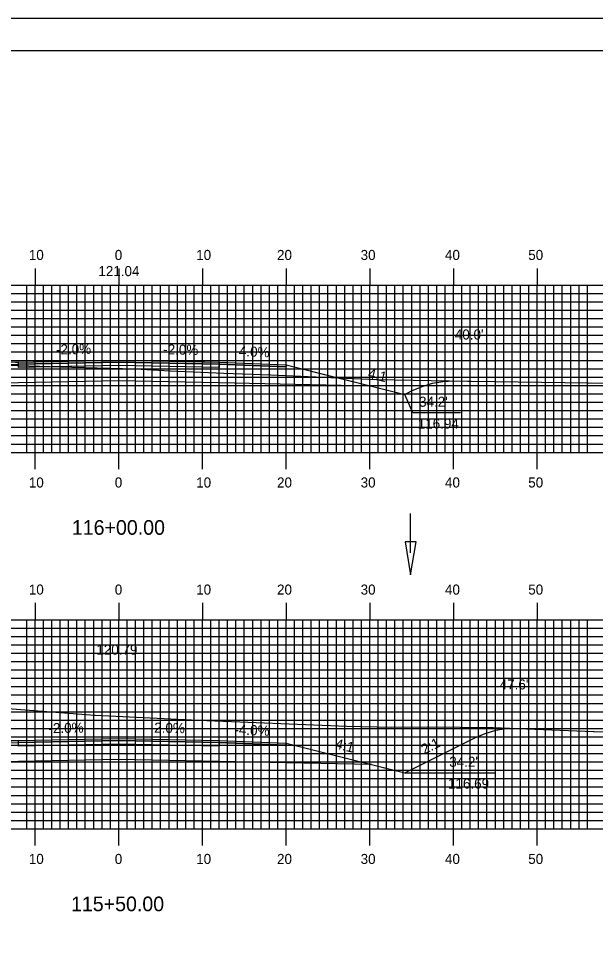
# Model space of a CAD drawing. Extents: x 1770842 to 1771185, y 442591 to 442811.
# Drawn here: x 1770995.6 to 1771064.5, y 442700.5 to 442810.5 of the extents above; entities that cross this region are included whole.
import ezdxf

# ---------------------------------------------------------------- set-up
doc = ezdxf.new("R2010")
doc.units = 0
for name, color, linetype in [('ANNOTATION', 7, 'Continuous'), ('BORDER', 7, 'Continuous'), ('D_Drainage_Ditch_Line', 7, 'Continuous'), ('D_Roadway_Centerline', 7, 'Continuous'), ('D_Roadway_Centerline_Text', 7, 'Continuous'), ('D_Roadway_Edge_Shoulder', 7, 'Continuous'), ('D_Roadway_Edge_TW', 7, 'Continuous'), ('D_Roadway_Pavement', 7, 'Continuous'), ('D_Roadway_SlopeLines', 7, 'Continuous'), ('D_Roadway_SubGrade', 7, 'Continuous'), ('D_Text_Standard', 7, 'Continuous'), ('H_V ANNOTATION', 7, 'Continuous'), ('MAJOR', 7, 'Continuous'), ('MINOR', 7, 'Continuous'), ('PDRAIN', 7, 'Continuous'), ('PLOT BOUNDARY', 7, 'Continuous'), ('S_Roadway_Centerline', 7, 'Continuous')]:
    doc.layers.add(name, color=color, linetype=linetype)

msp = doc.modelspace()

# ---------------------------------------------------------------- linework, layer by layer
at = {"layer": 'ANNOTATION'}
msp.add_lwpolyline([(1771048.38, 442763.4), (1771042.69, 442763.4), (1771041.73, 442765.6)], dxfattribs=at)
at = {"layer": 'BORDER'}
msp.add_lwpolyline([(1770857.95, 442596.67), (1771177.95, 442596.67), (1771177.95, 442806.67), (1770857.95, 442806.67)], close=True, dxfattribs=at)
at = {"layer": 'D_Drainage_Ditch_Line'}
msp.add_line((1771042.42, 442746.66), (1771042.42, 442751.36), dxfattribs=at)
msp.add_lwpolyline([(1771043.07, 442747.97), (1771041.76, 442747.97), (1771042.42, 442744.03)], close=True, dxfattribs=at)
at = {"layer": 'D_Roadway_Centerline'}
for points in [[(1770995.21, 442769.45), (1770995.55, 442769.47), (1770997.35, 442769.5), (1771007.55, 442769.71), (1771010.77, 442769.64), (1771019.55, 442769.47), (1771027.55, 442769.15), (1771033.74, 442767.6), (1771037.73, 442766.6), (1771041.73, 442765.6), (1771042.54, 442766.01), (1771043.79, 442766.55), (1771045.04, 442766.93), (1771046.29, 442767.15), (1771047.43, 442767.21), (1771047.54, 442767.21)], [(1770993.94, 442724.15), (1770995.55, 442724.22), (1770995.56, 442724.22), (1771007.55, 442724.46), (1771007.56, 442724.46), (1771019.55, 442724.22), (1771019.56, 442724.22), (1771022.63, 442724.09), (1771027.55, 442723.9), (1771037.73, 442721.35), (1771040.09, 442720.76), (1771041.73, 442720.35), (1771050.1, 442724.54), (1771051.35, 442725.08), (1771052.6, 442725.45), (1771053.85, 442725.65), (1771055.1, 442725.68)]]:
    msp.add_lwpolyline(points, dxfattribs=at)
at = {"layer": 'D_Roadway_Edge_Shoulder'}
for points in [[(1770995.55, 442769.47), (1770987.55, 442769.15), (1770987.55, 442768.9), (1770995.55, 442769.22)], [(1771019.55, 442769.47), (1771027.55, 442769.15), (1771027.55, 442768.9), (1771019.55, 442769.22)], [(1770995.55, 442724.22), (1770987.55, 442723.9), (1770987.55, 442723.65), (1770995.55, 442723.97)], [(1771019.55, 442724.22), (1771027.55, 442723.9), (1771027.55, 442723.65), (1771019.55, 442723.97)]]:
    msp.add_lwpolyline(points, close=True, dxfattribs=at)
at = {"layer": 'D_Roadway_Edge_TW'}
for points in [[(1770995.55, 442769.22), (1770995.55, 442769.47), (1771007.55, 442769.71), (1771019.55, 442769.47), (1771019.55, 442769.22), (1771007.55, 442769.46)], [(1770995.55, 442723.97), (1770995.55, 442724.22), (1771007.55, 442724.46), (1771019.55, 442724.22), (1771019.55, 442723.97), (1771007.55, 442724.21)]]:
    msp.add_lwpolyline(points, close=True, dxfattribs=at)
at = {"layer": 'D_Roadway_Pavement'}
for points in [[(1770995.55, 442768.8), (1770995.55, 442769.22), (1771007.55, 442769.46), (1771019.55, 442769.22), (1771019.55, 442768.8), (1771007.55, 442769.04)], [(1770995.55, 442723.55), (1770995.55, 442723.97), (1771007.55, 442724.21), (1771019.55, 442723.97), (1771019.55, 442723.55), (1771007.55, 442723.79)]]:
    msp.add_lwpolyline(points, close=True, dxfattribs=at)
at = {"layer": 'D_Roadway_SlopeLines'}
for points in [[(1771027.55, 442769.15), (1771041.73, 442765.6)], [(1771041.73, 442765.6), (1771042.54, 442766.01), (1771043.79, 442766.55), (1771045.04, 442766.93), (1771046.29, 442767.15), (1771047.54, 442767.21)], [(1771041.73, 442720.35), (1771050.1, 442724.54), (1771051.35, 442725.08), (1771052.6, 442725.45), (1771053.85, 442725.65), (1771055.1, 442725.68)], [(1771027.55, 442723.9), (1771041.73, 442720.35)]]:
    msp.add_lwpolyline(points, dxfattribs=at)
at = {"layer": 'D_Roadway_SubGrade'}
for points in [[(1770995.55, 442766.97), (1770977.38, 442766.6), (1770987.55, 442769.15), (1770987.55, 442768.9), (1770995.55, 442769.22), (1771007.55, 442769.46), (1771019.55, 442769.22), (1771027.55, 442768.9), (1771027.55, 442769.15), (1771037.73, 442766.6), (1771019.55, 442766.97), (1771007.55, 442767.21)], [(1770995.55, 442721.72), (1770977.38, 442721.35), (1770987.55, 442723.9), (1770987.55, 442723.65), (1770995.55, 442723.97), (1771007.55, 442724.21), (1771019.55, 442723.97), (1771027.55, 442723.65), (1771027.55, 442723.9), (1771037.73, 442721.35), (1771019.55, 442721.72), (1771007.55, 442721.96)]]:
    msp.add_lwpolyline(points, close=True, dxfattribs=at)
at = {"layer": 'MAJOR'}
for p, q in [((1770997.55, 442780.67), (1770997.55, 442778.67)), ((1771007.55, 442780.67), (1771007.55, 442778.67)), ((1771017.55, 442780.67), (1771017.55, 442778.67)), ((1771027.55, 442780.67), (1771027.55, 442778.67)), ((1771037.55, 442780.67), (1771037.55, 442778.67)), ((1771047.55, 442780.67), (1771047.55, 442778.67)), ((1771057.55, 442780.67), (1771057.55, 442778.67)), ((1770867.55, 442778.67), (1771147.55, 442778.67)), ((1770867.55, 442778.67), (1771147.55, 442778.67)), ((1770997.55, 442758.67), (1770997.55, 442778.67)), ((1771007.55, 442758.67), (1771007.55, 442778.67)), ((1771017.55, 442758.67), (1771017.55, 442778.67)), ((1771027.55, 442758.67), (1771027.55, 442778.67)), ((1771037.55, 442758.67), (1771037.55, 442778.67)), ((1771047.55, 442758.67), (1771047.55, 442778.67)), ((1771057.55, 442758.67), (1771057.55, 442778.67)), ((1770867.55, 442773.67), (1771147.55, 442773.67)), ((1770867.55, 442768.67), (1771147.55, 442768.67)), ((1770867.55, 442763.67), (1771147.55, 442763.67)), ((1770867.55, 442758.67), (1771147.55, 442758.67)), ((1770867.55, 442758.67), (1771147.55, 442758.67)), ((1770997.55, 442756.66), (1770997.55, 442758.67)), ((1771007.55, 442756.66), (1771007.55, 442758.67)), ((1771017.55, 442756.66), (1771017.55, 442758.67)), ((1771027.55, 442756.66), (1771027.55, 442758.67)), ((1771037.55, 442756.66), (1771037.55, 442758.67)), ((1771047.55, 442756.66), (1771047.55, 442758.67)), ((1771057.55, 442756.66), (1771057.55, 442758.67)), ((1770997.55, 442740.67), (1770997.55, 442738.67)), ((1771007.55, 442740.67), (1771007.55, 442738.67)), ((1771017.55, 442740.67), (1771017.55, 442738.67)), ((1771027.55, 442740.67), (1771027.55, 442738.67)), ((1771037.55, 442740.67), (1771037.55, 442738.67)), ((1771047.55, 442740.67), (1771047.55, 442738.67)), ((1771057.55, 442740.67), (1771057.55, 442738.67)), ((1770867.55, 442738.67), (1771147.55, 442738.67)), ((1770867.55, 442738.67), (1771147.55, 442738.67)), ((1770997.55, 442713.67), (1770997.55, 442738.67)), ((1771007.55, 442713.67), (1771007.55, 442738.67)), ((1771017.55, 442713.67), (1771017.55, 442738.67)), ((1771027.55, 442713.67), (1771027.55, 442738.67)), ((1771037.55, 442713.67), (1771037.55, 442738.67)), ((1771047.55, 442713.67), (1771047.55, 442738.67)), ((1771057.55, 442713.67), (1771057.55, 442738.67)), ((1770867.55, 442733.67), (1771147.55, 442733.67)), ((1770867.55, 442728.67), (1771147.55, 442728.67)), ((1770867.55, 442723.67), (1771147.55, 442723.67)), ((1770867.55, 442718.67), (1771147.55, 442718.67)), ((1770867.55, 442713.67), (1771147.55, 442713.67)), ((1770867.55, 442713.67), (1771147.55, 442713.67)), ((1770997.55, 442711.66), (1770997.55, 442713.67)), ((1771007.55, 442711.66), (1771007.55, 442713.67)), ((1771017.55, 442711.66), (1771017.55, 442713.67)), ((1771027.55, 442711.66), (1771027.55, 442713.67)), ((1771037.55, 442711.66), (1771037.55, 442713.67)), ((1771047.55, 442711.66), (1771047.55, 442713.67)), ((1771057.55, 442711.66), (1771057.55, 442713.67))]:
    msp.add_line(p, q, dxfattribs=at)
at = {"layer": 'MINOR'}
for p, q in [((1770996.55, 442758.67), (1770996.55, 442778.67)), ((1770998.55, 442758.67), (1770998.55, 442778.67)), ((1770999.55, 442758.67), (1770999.55, 442778.67)), ((1771000.55, 442758.67), (1771000.55, 442778.67)), ((1771001.55, 442758.67), (1771001.55, 442778.67)), ((1771002.55, 442758.67), (1771002.55, 442778.67)), ((1771003.55, 442758.67), (1771003.55, 442778.67)), ((1771004.55, 442758.67), (1771004.55, 442778.67)), ((1771005.55, 442758.67), (1771005.55, 442778.67)), ((1771006.55, 442758.67), (1771006.55, 442778.67)), ((1771008.55, 442758.67), (1771008.55, 442778.67)), ((1771009.55, 442758.67), (1771009.55, 442778.67)), ((1771010.55, 442758.67), (1771010.55, 442778.67)), ((1771011.55, 442758.67), (1771011.55, 442778.67)), ((1771012.55, 442758.67), (1771012.55, 442778.67)), ((1771013.55, 442758.67), (1771013.55, 442778.67)), ((1771014.55, 442758.67), (1771014.55, 442778.67)), ((1771015.55, 442758.67), (1771015.55, 442778.67)), ((1771016.55, 442758.67), (1771016.55, 442778.67)), ((1771018.55, 442758.67), (1771018.55, 442778.67)), ((1771019.55, 442758.67), (1771019.55, 442778.67)), ((1771020.55, 442758.67), (1771020.55, 442778.67)), ((1771021.55, 442758.67), (1771021.55, 442778.67)), ((1771022.55, 442758.67), (1771022.55, 442778.67)), ((1771023.55, 442758.67), (1771023.55, 442778.67)), ((1771024.55, 442758.67), (1771024.55, 442778.67)), ((1771025.55, 442758.67), (1771025.55, 442778.67)), ((1771026.55, 442758.67), (1771026.55, 442778.67)), ((1771028.55, 442758.67), (1771028.55, 442778.67)), ((1771029.55, 442758.67), (1771029.55, 442778.67)), ((1771030.55, 442758.67), (1771030.55, 442778.67)), ((1771031.55, 442758.67), (1771031.55, 442778.67)), ((1771032.55, 442758.67), (1771032.55, 442778.67)), ((1771033.55, 442758.67), (1771033.55, 442778.67)), ((1771034.55, 442758.67), (1771034.55, 442778.67)), ((1771035.55, 442758.67), (1771035.55, 442778.67)), ((1771036.55, 442758.67), (1771036.55, 442778.67)), ((1771038.55, 442758.67), (1771038.55, 442778.67)), ((1771039.55, 442758.67), (1771039.55, 442778.67)), ((1771040.55, 442758.67), (1771040.55, 442778.67)), ((1771041.55, 442758.67), (1771041.55, 442778.67)), ((1771042.55, 442758.67), (1771042.55, 442778.67)), ((1771043.55, 442758.67), (1771043.55, 442778.67)), ((1771044.55, 442758.67), (1771044.55, 442778.67)), ((1771045.55, 442758.67), (1771045.55, 442778.67)), ((1771046.55, 442758.67), (1771046.55, 442778.67)), ((1771048.55, 442758.67), (1771048.55, 442778.67)), ((1771049.55, 442758.67), (1771049.55, 442778.67)), ((1771050.55, 442758.67), (1771050.55, 442778.67)), ((1771051.55, 442758.67), (1771051.55, 442778.67)), ((1771052.55, 442758.67), (1771052.55, 442778.67)), ((1771053.55, 442758.67), (1771053.55, 442778.67)), ((1771054.55, 442758.67), (1771054.55, 442778.67)), ((1771055.55, 442758.67), (1771055.55, 442778.67)), ((1771056.55, 442758.67), (1771056.55, 442778.67)), ((1771058.55, 442758.67), (1771058.55, 442778.67)), ((1771059.55, 442758.67), (1771059.55, 442778.67)), ((1771060.55, 442758.67), (1771060.55, 442778.67)), ((1771061.55, 442758.67), (1771061.55, 442778.67)), ((1771062.55, 442758.67), (1771062.55, 442778.67)), ((1771063.55, 442758.67), (1771063.55, 442778.67)), ((1770867.55, 442777.67), (1771147.55, 442777.67)), ((1770867.55, 442776.67), (1771147.55, 442776.67)), ((1770867.55, 442775.67), (1771147.55, 442775.67)), ((1770867.55, 442774.67), (1771147.55, 442774.67)), ((1770867.55, 442772.67), (1771147.55, 442772.67)), ((1770867.55, 442771.67), (1771147.55, 442771.67)), ((1770867.55, 442770.67), (1771147.55, 442770.67)), ((1770867.55, 442769.67), (1771147.55, 442769.67)), ((1770867.55, 442767.67), (1771147.55, 442767.67)), ((1770867.55, 442766.67), (1771147.55, 442766.67)), ((1770867.55, 442765.67), (1771147.55, 442765.67)), ((1770867.55, 442764.67), (1771147.55, 442764.67)), ((1770867.55, 442762.67), (1771147.55, 442762.67)), ((1770867.55, 442761.67), (1771147.55, 442761.67)), ((1770867.55, 442760.67), (1771147.55, 442760.67)), ((1770867.55, 442759.67), (1771147.55, 442759.67)), ((1770996.55, 442713.67), (1770996.55, 442738.67)), ((1770998.55, 442713.67), (1770998.55, 442738.67)), ((1770999.55, 442713.67), (1770999.55, 442738.67)), ((1771000.55, 442713.67), (1771000.55, 442738.67)), ((1771001.55, 442713.67), (1771001.55, 442738.67)), ((1771002.55, 442713.67), (1771002.55, 442738.67)), ((1771003.55, 442713.67), (1771003.55, 442738.67)), ((1771004.55, 442713.67), (1771004.55, 442738.67)), ((1771005.55, 442713.67), (1771005.55, 442738.67)), ((1771006.55, 442713.67), (1771006.55, 442738.67)), ((1771008.55, 442713.67), (1771008.55, 442738.67)), ((1771009.55, 442713.67), (1771009.55, 442738.67)), ((1771010.55, 442713.67), (1771010.55, 442738.67)), ((1771011.55, 442713.67), (1771011.55, 442738.67)), ((1771012.55, 442713.67), (1771012.55, 442738.67)), ((1771013.55, 442713.67), (1771013.55, 442738.67)), ((1771014.55, 442713.67), (1771014.55, 442738.67)), ((1771015.55, 442713.67), (1771015.55, 442738.67)), ((1771016.55, 442713.67), (1771016.55, 442738.67)), ((1771018.55, 442713.67), (1771018.55, 442738.67)), ((1771019.55, 442713.67), (1771019.55, 442738.67)), ((1771020.55, 442713.67), (1771020.55, 442738.67)), ((1771021.55, 442713.67), (1771021.55, 442738.67)), ((1771022.55, 442713.67), (1771022.55, 442738.67)), ((1771023.55, 442713.67), (1771023.55, 442738.67)), ((1771024.55, 442713.67), (1771024.55, 442738.67)), ((1771025.55, 442713.67), (1771025.55, 442738.67)), ((1771026.55, 442713.67), (1771026.55, 442738.67)), ((1771028.55, 442713.67), (1771028.55, 442738.67)), ((1771029.55, 442713.67), (1771029.55, 442738.67)), ((1771030.55, 442713.67), (1771030.55, 442738.67)), ((1771031.55, 442713.67), (1771031.55, 442738.67)), ((1771032.55, 442713.67), (1771032.55, 442738.67)), ((1771033.55, 442713.67), (1771033.55, 442738.67)), ((1771034.55, 442713.67), (1771034.55, 442738.67)), ((1771035.55, 442713.67), (1771035.55, 442738.67)), ((1771036.55, 442713.67), (1771036.55, 442738.67)), ((1771038.55, 442713.67), (1771038.55, 442738.67)), ((1771039.55, 442713.67), (1771039.55, 442738.67)), ((1771040.55, 442713.67), (1771040.55, 442738.67)), ((1771041.55, 442713.67), (1771041.55, 442738.67)), ((1771042.55, 442713.67), (1771042.55, 442738.67)), ((1771043.55, 442713.67), (1771043.55, 442738.67)), ((1771044.55, 442713.67), (1771044.55, 442738.67)), ((1771045.55, 442713.67), (1771045.55, 442738.67)), ((1771046.55, 442713.67), (1771046.55, 442738.67)), ((1771048.55, 442713.67), (1771048.55, 442738.67)), ((1771049.55, 442713.67), (1771049.55, 442738.67)), ((1771050.55, 442713.67), (1771050.55, 442738.67)), ((1771051.55, 442713.67), (1771051.55, 442738.67)), ((1771052.55, 442713.67), (1771052.55, 442738.67)), ((1771053.55, 442713.67), (1771053.55, 442738.67)), ((1771054.55, 442713.67), (1771054.55, 442738.67)), ((1771055.55, 442713.67), (1771055.55, 442738.67)), ((1771056.55, 442713.67), (1771056.55, 442738.67)), ((1771058.55, 442713.67), (1771058.55, 442738.67)), ((1771059.55, 442713.67), (1771059.55, 442738.67)), ((1771060.55, 442713.67), (1771060.55, 442738.67)), ((1771061.55, 442713.67), (1771061.55, 442738.67)), ((1771062.55, 442713.67), (1771062.55, 442738.67)), ((1771063.55, 442713.67), (1771063.55, 442738.67)), ((1770867.55, 442737.67), (1771147.55, 442737.67)), ((1770867.55, 442736.67), (1771147.55, 442736.67)), ((1770867.55, 442735.67), (1771147.55, 442735.67)), ((1770867.55, 442734.67), (1771147.55, 442734.67)), ((1770867.55, 442732.67), (1771147.55, 442732.67)), ((1770867.55, 442731.67), (1771147.55, 442731.67)), ((1770867.55, 442730.67), (1771147.55, 442730.67)), ((1770867.55, 442729.67), (1771147.55, 442729.67)), ((1770867.55, 442727.67), (1771147.55, 442727.67)), ((1770867.55, 442726.67), (1771147.55, 442726.67)), ((1770867.55, 442725.67), (1771147.55, 442725.67)), ((1770867.55, 442724.67), (1771147.55, 442724.67)), ((1770867.55, 442722.67), (1771147.55, 442722.67)), ((1770867.55, 442721.67), (1771147.55, 442721.67)), ((1770867.55, 442720.67), (1771147.55, 442720.67)), ((1770867.55, 442719.67), (1771147.55, 442719.67)), ((1770867.55, 442717.67), (1771147.55, 442717.67)), ((1770867.55, 442716.67), (1771147.55, 442716.67)), ((1770867.55, 442715.67), (1771147.55, 442715.67)), ((1770867.55, 442714.67), (1771147.55, 442714.67))]:
    msp.add_line(p, q, dxfattribs=at)
at = {"layer": 'PDRAIN'}
msp.add_line((1771041.73, 442720.35), (1771052.5, 442720.35), dxfattribs=at)
at = {"layer": 'PLOT BOUNDARY'}
msp.add_lwpolyline([(1770841.77, 442590.55), (1771181.77, 442590.55), (1771181.77, 442810.55), (1770841.77, 442810.55)], close=True, dxfattribs=at)
at = {"layer": 'S_Roadway_Centerline'}
for points in [[(1770933.71, 442771.31), (1770950.3, 442771.19), (1770961.31, 442770.9), (1770969.16, 442770.62), (1770978.29, 442769.86), (1770990.16, 442769.22), (1770991.62, 442769.16), (1771001.93, 442768.85), (1771009.49, 442768.67), (1771013.67, 442768.4), (1771020.09, 442768.15), (1771025.72, 442767.92), (1771030.17, 442767.73), (1771038.35, 442767.38), (1771049.28, 442767.18), (1771049.65, 442767.18), (1771069.27, 442766.89)], [(1770933.69, 442729.93), (1770944.44, 442729.3), (1770945.31, 442729.29), (1770946.7, 442729.26), (1770958.32, 442729.09), (1770965.48, 442728.91), (1770975.35, 442728.38), (1770979.99, 442728.18), (1770983.6, 442728.14), (1770993.2, 442728.13), (1771004.67, 442727.27), (1771004.7, 442727.26), (1771004.71, 442727.26), (1771017.09, 442726.64), (1771034.82, 442725.93), (1771040.18, 442725.84), (1771044.39, 442725.86), (1771052.3, 442725.8), (1771064.28, 442725.3), (1771064.35, 442725.29), (1771083.72, 442724.92)]]:
    msp.add_lwpolyline(points, dxfattribs=at)

# ---------------------------------------------------------------- texts
at = {"layer": 'ANNOTATION'}
for s, rotation, p in [('-2.0%', 1.1458, (1771000.06, 442770.36)), ('-2.0%', 358.8543, (1771012.85, 442770.4)), ('-4.0%', 357.7093, (1771021.35, 442770.2)), ('4:1', 345.9626, (1771037.24, 442767.59)), ('-2.0%', 1.1457, (1770999.16, 442725.09)), ('-2.0%', 358.8543, (1771011.24, 442725.18)), ('-4.0%', 357.7092, (1771021.35, 442724.95)), ('4:1', 345.9615, (1771033.33, 442723.31)), ('2:1', 26.5661, (1771044.06, 442722.55))]:
    msp.add_text(s, height=1.2, rotation=rotation, dxfattribs=at).set_placement(p)
for s, p in [("34.2'", (1771043.43, 442764.12)), ('116.94', (1771043.28, 442761.52)), ("34.2'", (1771047.04, 442721.08)), ('116.69', (1771046.89, 442718.48))]:
    msp.add_text(s, height=1.2, dxfattribs=at).set_placement(p)
at = {"layer": 'D_Roadway_Centerline'}
for s, p in [('C', (1771007.55, 442769.71)), ('L', (1771007.55, 442769.7)), ('C', (1771007.55, 442724.46)), ('L', (1771007.55, 442724.45))]:
    msp.add_text(s, height=0.0146, dxfattribs=at).set_placement(p)
at = {"layer": 'D_Roadway_Centerline_Text'}
for s, p in [('121.04', (1771005.11, 442779.74)), ('120.79', (1771004.87, 442734.49))]:
    msp.add_text(s, height=1.2, dxfattribs=at).set_placement(p)
at = {"layer": 'D_Text_Standard'}
for s, p in [("40.0'", (1771047.71, 442772.16)), ("47.6'", (1771053.07, 442730.33))]:
    msp.add_text(s, height=1.2, dxfattribs=at).set_placement(p)
at = {"layer": 'H_V ANNOTATION'}
for s, height, p in [('10', 1.2, (1770996.8, 442781.67)), ('0', 1.2, (1771007.07, 442781.67)), ('10', 1.2, (1771016.8, 442781.67)), ('20', 1.2, (1771026.46, 442781.67)), ('30', 1.2, (1771036.45, 442781.67)), ('40', 1.2, (1771046.53, 442781.67)), ('50', 1.2, (1771056.48, 442781.67)), ('10', 1.2, (1770996.8, 442754.47)), ('0', 1.2, (1771007.07, 442754.47)), ('10', 1.2, (1771016.8, 442754.47)), ('20', 1.2, (1771026.46, 442754.47)), ('30', 1.2, (1771036.45, 442754.47)), ('40', 1.2, (1771046.53, 442754.47)), ('50', 1.2, (1771056.48, 442754.47)), ('116+00.00', 1.75, (1771001.94, 442748.82)), ('10', 1.2, (1770996.8, 442741.67)), ('0', 1.2, (1771007.07, 442741.67)), ('10', 1.2, (1771016.8, 442741.67)), ('20', 1.2, (1771026.46, 442741.67)), ('30', 1.2, (1771036.45, 442741.67)), ('40', 1.2, (1771046.53, 442741.67)), ('50', 1.2, (1771056.48, 442741.67)), ('10', 1.2, (1770996.8, 442709.47)), ('0', 1.2, (1771007.07, 442709.47)), ('10', 1.2, (1771016.8, 442709.47)), ('20', 1.2, (1771026.46, 442709.47)), ('30', 1.2, (1771036.45, 442709.47)), ('40', 1.2, (1771046.53, 442709.47)), ('50', 1.2, (1771056.48, 442709.47)), ('115+50.00', 1.75, (1771001.84, 442703.82))]:
    msp.add_text(s, height=height, dxfattribs=at).set_placement(p)

doc.saveas('drawing.dxf')
